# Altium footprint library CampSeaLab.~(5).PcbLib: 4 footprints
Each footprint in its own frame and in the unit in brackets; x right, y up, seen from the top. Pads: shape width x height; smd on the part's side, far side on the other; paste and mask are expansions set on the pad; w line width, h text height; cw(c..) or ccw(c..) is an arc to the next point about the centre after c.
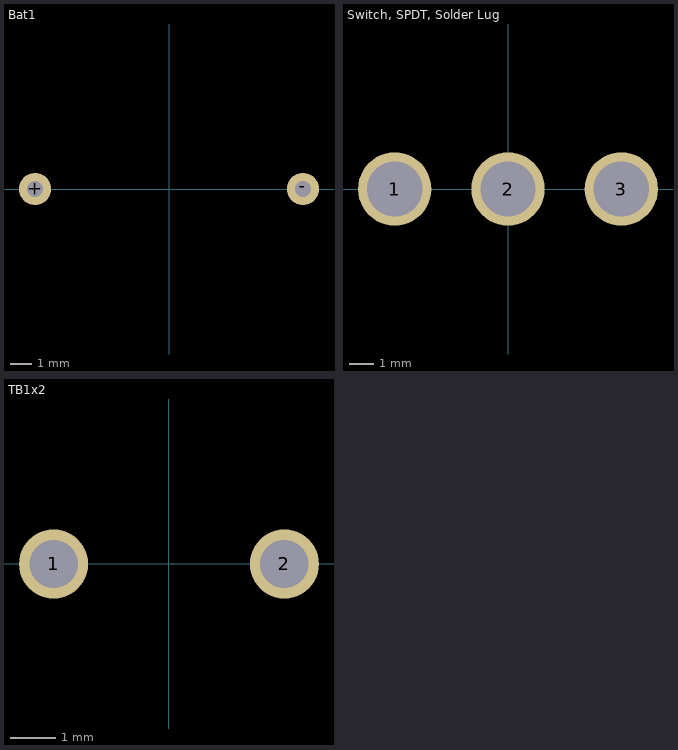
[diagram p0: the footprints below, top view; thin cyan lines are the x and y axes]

## Bat1 [mil] "Battery Holder 2xAA"
pads (2):
  round 60 hole 30: +(-250,0) -(250,0)

## PCBComponent_1 [mil]

## Switch, SPDT, Solder Lug [mil]
pads (3):
  round 120 hole 90: 1(-185,0) 2(0,0) 3(185,0)

## TB1x2 [mil]
pads (2):
  round 60 hole 42: 1(-100,0) 2(100,0)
